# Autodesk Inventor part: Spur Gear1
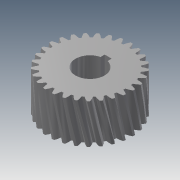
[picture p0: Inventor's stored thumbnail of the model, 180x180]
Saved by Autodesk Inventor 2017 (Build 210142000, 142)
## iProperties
Created: 2019-03
Part Number: Spur Gear1
Material: Steel
Document SubType Name: Modeling
Designer: user
Categories: <?xml version="1.0" encoding="UTF-16"?> <MemberInstance><Categories><FamilyTemplate><FamilyTemplateParameter ValueType="xs:double" Id="1" ObjectReferenceKey="da
Density: 1 g/cm^3
Appearance: Steel
CustomPartVersion: 1
Author: user
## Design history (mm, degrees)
sketch "Sketch1"
  geometry: C1 r 31.647 at (0, 0)
  constraints: 1 centre point
  dimensions: "d0" = 63.29459 diameter of C1 (= da_da)
extrude "Extrusion1" new body sketch "Sketch1" distance "d1" = 30 (= da_b); taper "d2" = 0 deg
workplane "Work Plane2"
sketch "Sketch2"
  geometry: C1 r 31.647 at (0, 0) reference; C2 r 28.663 at (0, 0)
  constraints: 1 centre point, 1 coincident
  dimensions: "d3" = 57.32558 diameter of C2 (= da_dw)
feature "Pitch Diameter" sketch "Sketch2" dims "d4" = 10, "d5" = 0
workplane "Work Plane8"
workplane "Work Plane9"
feature "Spur Gear" dims "d4" = 10, "da_b" = 30, "da_d" = 59.29575, "da_aw" = 85, "da_da" = 63.29459, "da_df" = 55.09575, "da_dw" = 57.32558, angle "da_beta" = 12 deg, "da_lefttooth" = 10, "da_righttooth" = 0
sketch "Sketch3"
  geometry: L1 (2.654, 10.675)-(2.654, 13.789); L2 (2.654, 13.789)-(-2.654, 13.789); L3 (-2.654, 13.789)-(-2.654, 10.675); A1 r 11 centre (0, 0) between (-2.654, 10.675) and (2.654, 10.675); 2 further points
  constraints: 6 end point, 2 point on circle, 1 centre point, 1 coincident, 1 midpoint, 1 parallel, 1 vertical alignment
  dimensions: "d49" = 22 diameter of A1
extrude "Extrusion2" cut sketch "Sketch3" stored distance "d50" = 10; taper "d51" = 0 deg
body "Solid1"
body "Srf1"
other parameters: "d16" = 85 (= da_aw), "d17" = 0, "d34" = 1.08331 (computed from da_z), "d39" = 0, "d41" = 0, "d43" = 85 (= da_aw), "d46" = 85 (= da_aw), "d47" = 0, "d48" = 0
